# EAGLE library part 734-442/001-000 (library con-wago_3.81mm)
Serie 734, Doppelstock-Stiftleisten Einlötstift abgewinkelt 1 x 1 mm / Series 734, Double-deck male headers Angled solder pin 1 x 1 mm Polzahl / Pole No.: 12 Rastermaß / Pitch: 3.81 mm Bemessungsspannung / Rated Voltage: 160 V Nennstrom / Nominal Current: 10 A Lötstiftlänge: / Solder Pin Length: 3.6 mm Farbe / Color: orange / orange Stand: 01.01.2012. Die jeweils aktuellen Daten zu diesem Artikel finden Sie in unserem Produktkatalog, den Sie unter www.wago.com einsehen können. As of: 01/01/2012. Please find the newest data for this article in our product catalogue, which can be viewed under www.wago.com.
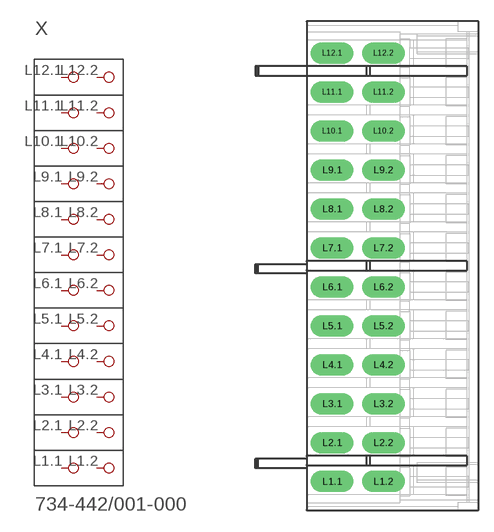
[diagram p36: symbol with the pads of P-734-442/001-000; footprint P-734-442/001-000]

Designator prefix X

## 734-442/001-000  [P-734-442/001-000]
L1.1  P1.1
L1.2  P1.2
L2.1  P2.1
L2.2  P2.2
L3.1  P3.1
L3.2  P3.2
L4.1  P4.1
L4.2  P4.2
L5.1  P5.1
L5.2  P5.2
L6.1  P6.1
L6.2  P6.2
L7.1  P7.1
L7.2  P7.2
L8.1  P8.1
L8.2  P8.2
L9.1  P9.1
L9.2  P9.2
L10.1  P10.1
L10.2  P10.2
L11.1  P11.1
L11.2  P11.2
L12.1  P12.1
L12.2  P12.2

## Footprint P-734-442/001-000 (pad centres in mm)
drill 1.4 long: L1.1 -3.4,-21.095; L1.2 1.6,-21.095; L2.1 -3.4,-17.295; L2.2 1.6,-17.295; L3.1 -3.4,-13.485; L3.2 1.6,-13.485; L4.1 -3.4,-9.675; L4.2 1.6,-9.675; L5.1 -3.4,-5.875; L5.2 1.6,-5.875; L6.1 -3.4,-2.065; L6.2 1.6,-2.065; L7.1 -3.4,1.755; L7.2 1.6,1.755; L8.1 -3.4,5.565; L8.2 1.6,5.565; L9.1 -3.4,9.375; L9.2 1.6,9.375; L10.1 -3.4,13.185; L10.2 1.6,13.185; L11.1 -3.4,16.995; L11.2 1.6,16.995; L12.1 -3.4,20.805; L12.2 1.6,20.805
